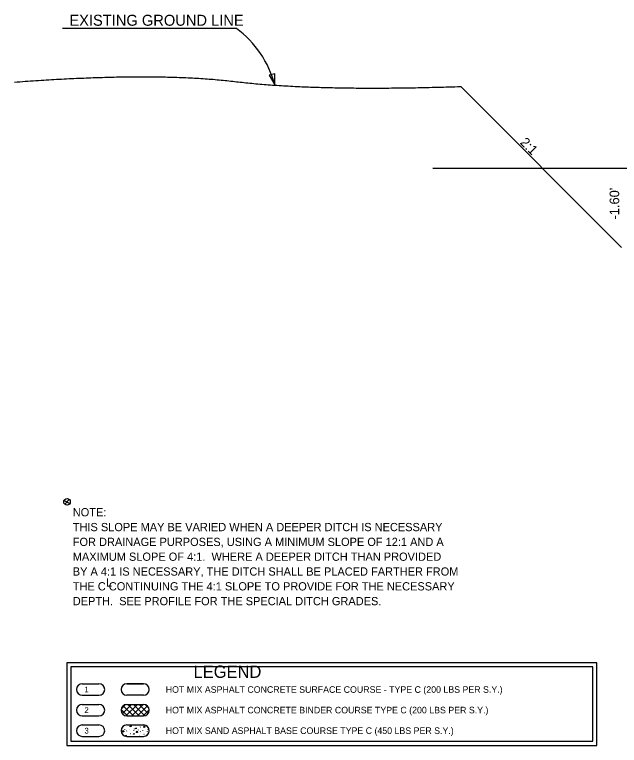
# Model space of a CAD drawing. Extents: x -859 to 797, y 1810 to 2851.
# Drawn here: x -859 to -418, y 1911 to 2444 of the extents above; entities that cross this region are included whole.
import ezdxf

# ---------------------------------------------------------------- set-up
doc = ezdxf.new("R2010")
doc.units = 0
doc.layers.add('Level 41', color=7, linetype='Continuous')

msp = doc.modelspace()

# ---------------------------------------------------------------- linework, layer by layer
at = {"layer": 'Level 41'}
for p, q in [((-697.65, 2433.61), (-824.48, 2433.61)), ((-533.89, 2391.32), (-416.65, 2274.09)), ((-554.3, 2331.73), (338.21, 2331.73)), ((-823.35, 2089.59), (-819.06, 2087.4)), ((-822.86, 2086.82), (-819.55, 2090.19)), ((-810.04, 1955.96), (-797.9, 1955.96)), ((-777.5, 1955.96), (-765.36, 1955.96)), ((-765.36, 1955.96), (-777.5, 1955.96)), ((-777.5, 1955.96), (-765.36, 1955.96)), ((-810.04, 1947.56), (-797.9, 1947.56)), ((-765.36, 1947.56), (-777.5, 1947.56)), ((-810.04, 1940.96), (-797.9, 1940.96)), ((-781.56, 1937.73), (-778.44, 1940.84)), ((-780.82, 1934.23), (-774.09, 1940.96)), ((-780.19, 1939.97), (-772.78, 1932.56)), ((-778.16, 1932.64), (-769.84, 1940.96)), ((-777.5, 1940.96), (-765.36, 1940.96)), ((-776.94, 1940.96), (-768.54, 1932.56)), ((-774, 1932.56), (-765.6, 1940.96)), ((-772.7, 1940.96), (-764.41, 1932.67)), ((-769.76, 1932.56), (-762.49, 1939.82)), ((-768.46, 1940.96), (-761.9, 1934.4)), ((-763.93, 1940.68), (-761.4, 1938.15)), ((-781.66, 1937.2), (-777.03, 1932.56)), ((-765.52, 1932.56), (-761.19, 1936.88)), ((-810.04, 1932.56), (-797.9, 1932.56)), ((-777.5, 1932.56), (-765.36, 1932.56)), ((-810.04, 1925.96), (-797.9, 1925.96)), ((-777.78, 1924.94), (-777.68, 1925.13)), ((-777.5, 1925.96), (-765.36, 1925.96)), ((-772.22, 1923.07), (-772.14, 1922.93)), ((-771.11, 1925.5), (-771.02, 1925.69)), ((-767.79, 1924.41), (-767.69, 1924.61)), ((-779.25, 1922.87), (-779.17, 1922.73)), ((-777.74, 1921.38), (-777.64, 1921.57)), ((-775.9, 1922.26), (-775.8, 1922.45)), ((-775.05, 1919.82), (-774.96, 1919.68)), ((-772.46, 1921.61), (-772.36, 1921.81)), ((-769.26, 1922.35), (-769.18, 1922.21)), ((-767.76, 1920.86), (-767.66, 1921.05)), ((-765.91, 1921.73), (-765.81, 1921.93)), ((-765.06, 1919.29), (-764.98, 1919.15)), ((-762.48, 1921.09), (-762.38, 1921.29)), ((-762.23, 1922.54), (-762.15, 1922.41)), ((-810.04, 1917.56), (-797.9, 1917.56)), ((-777.5, 1917.56), (-765.36, 1917.56)), ((-772.92, 1917.57), (-772.92, 1917.56))]:
    msp.add_line(p, q, dxfattribs=at)
for points in [[(-673.62, 2399.48), (-669.69, 2392.51), (-669.6, 2400.51)], [(-821.39, 1911.04), (-434.63, 1911.04), (-434.63, 1971.19), (-821.39, 1971.19)], [(-818.39, 1914.04), (-437.63, 1914.04), (-437.63, 1968.19), (-818.39, 1968.19)]]:
    msp.add_lwpolyline(points, close=True, dxfattribs=at)
for points in [[(-780.85, 1924.2), (-780.46, 1923.88), (-781.11, 1923.71)], [(-775.09, 1924.56), (-774.85, 1925.82), (-774.1, 1924.96), (-775.07, 1924.57)], [(-771.19, 1923.17), (-770.9, 1923.71), (-770.47, 1923.35), (-771.19, 1923.17)], [(-765.11, 1924.04), (-764.87, 1925.3), (-764.11, 1924.44), (-765.09, 1924.05)], [(-780.77, 1920.94), (-780.11, 1922.04), (-779.7, 1920.97), (-780.75, 1920.94)], [(-778.59, 1917.83), (-778.3, 1918.37), (-777.87, 1918.02), (-778.59, 1917.83)], [(-772.75, 1919.12), (-772.45, 1919.66), (-772.03, 1919.3), (-772.75, 1919.12)], [(-770.78, 1920.41), (-770.12, 1921.51), (-769.71, 1920.45), (-770.76, 1920.41)], [(-768.47, 1917.56), (-768.31, 1917.85), (-767.96, 1917.56)], [(-762.76, 1918.59), (-762.47, 1919.13), (-762.27, 1918.97)], [(-762.75, 1918.6), (-762.76, 1918.59)]]:
    msp.add_lwpolyline(points, dxfattribs=at)
msp.add_circle((-821.19, 2088.52), 2.4, dxfattribs=at)
for centre, radius, start, end in [((-740.65, 2374.29), 73.27, 14.3993, 54.0589), ((-810.04, 1951.76), 4.2, 90, 270), ((-797.9, 1951.76), 4.2, 270, 90), ((-777.5, 1951.76), 4.2, 90, 270), ((-765.36, 1951.76), 4.2, 270, 90), ((-810.04, 1936.76), 4.2, 90, 270), ((-797.9, 1936.76), 4.2, 270, 90), ((-777.5, 1936.76), 4.2, 90, 270), ((-765.36, 1936.76), 4.2, 270, 90), ((-810.04, 1921.76), 4.2, 90, 270), ((-797.9, 1921.76), 4.2, 270, 90), ((-777.5, 1921.76), 4.2, 90, 270), ((-765.36, 1921.76), 4.2, 270, 90)]:
    msp.add_arc(centre, radius, start, end, dxfattribs=at)
msp.add_open_spline([(-859.43, 2394.57), (-757.96, 2402.12), (-639.71, 2387.85), (-533.89, 2391.32)], degree=2, dxfattribs=at)

# ---------------------------------------------------------------- texts
for s, height, p in [('EXISTING GROUND LINE', 8, (-819.48, 2435.61)), ('NOTE:', 6, (-816.99, 2077.99)), ('THIS SLOPE MAY BE VARIED WHEN A DEEPER DITCH IS NECESSARY', 6, (-816.99, 2067.19)), ('FOR DRAINAGE PURPOSES, USING A MINIMUM SLOPE OF 12:1 AND A', 6, (-816.99, 2056.39)), ('MAXIMUM SLOPE OF 4:1.  WHERE A DEEPER DITCH THAN PROVIDED', 6, (-816.99, 2045.59)), ('BY A 4:1 IS NECESSARY, THE DITCH SHALL BE PLACED FARTHER FROM', 6, (-816.99, 2034.79)), ('THE C CONTINUING THE 4:1 SLOPE TO PROVIDE FOR THE NECESSARY', 6, (-816.99, 2023.99)), ('L', 6, (-792.77, 2026.78)), ('DEPTH.  SEE PROFILE FOR THE SPECIAL DITCH GRADES.', 6, (-816.99, 2013.19)), ('LEGEND', 9, (-728.89, 1960.24)), (' 1 ', 4.2, (-810.04, 1949.66)), ('HOT MIX ASPHALT CONCRETE SURFACE COURSE - TYPE C (200 LBS PER S.Y.)', 4.8, (-749.16, 1949.36)), ('HOT MIX ASPHALT CONCRETE BINDER COURSE TYPE C (200 LBS PER S.Y.)', 4.8, (-749.16, 1934.36)), (' 2 ', 4.2, (-810.04, 1934.66)), (' 3 ', 4.2, (-810.04, 1919.66)), ('HOT MIX SAND ASPHALT BASE COURSE TYPE C (450 LBS PER S.Y.)', 4.8, (-749.16, 1919.36))]:
    msp.add_text(s, height=height, dxfattribs=at).set_placement(p)
for s, rotation, p in [('2:1', 315, (-491.12, 2350.04)), ("-1.60'", 90, (-418.33, 2294.39))]:
    msp.add_text(s, height=7, rotation=rotation, dxfattribs=at).set_placement(p)

doc.saveas('drawing.dxf')
